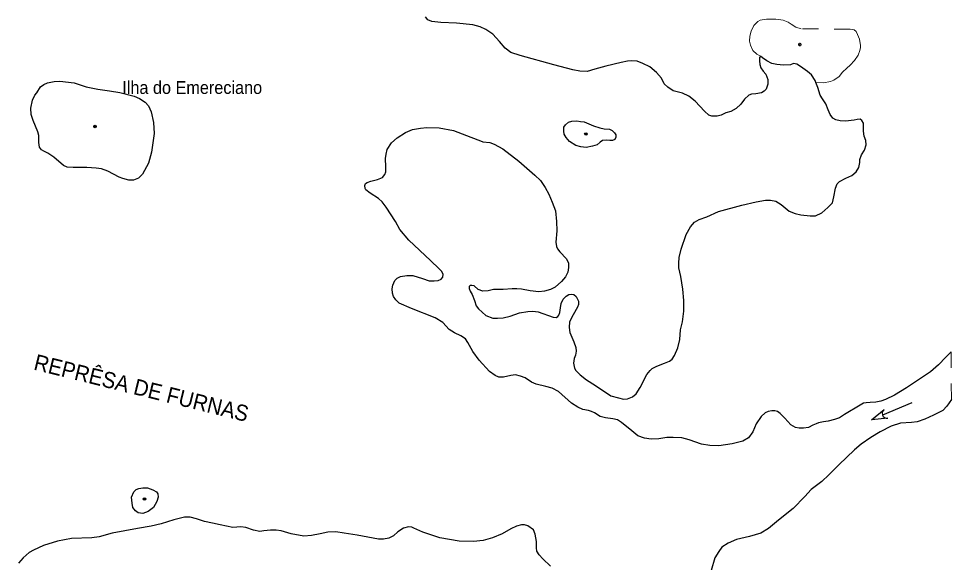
# Model space of a CAD drawing. Extents: x 396 to 422.2, y 7649.8 to 7677.6.
# Drawn here: x 416.25 to 422.09, y 7668.32 to 7671.72 of the extents above; entities that cross this region are included whole.
import ezdxf
from ezdxf.enums import TextEntityAlignment as Align

# ---------------------------------------------------------------- set-up
doc = ezdxf.new("R2010")
doc.units = 0
doc.header["$LTSCALE"] = 0.032
doc.header["$PDMODE"] = 32
doc.header["$PDSIZE"] = 0.016
doc.linetypes.add('SHORT_DASHED', pattern=[2.7, 1.5, -1.2])
for name, color, linetype, lineweight in [('10', 7, 'Continuous', 25), ('2', 7, 'Continuous', 25), ('21', 7, 'SHORT_DASHED', 13), ('62', 7, 'SHORT_DASHED', 13)]:
    doc.layers.add(name, color=color, linetype=linetype, lineweight=lineweight)
doc.layers.add('54', color=7, linetype='Continuous')
doc.layers.add('61', color=7, linetype='Continuous')

msp = doc.modelspace()

# ---------------------------------------------------------------- linework, layer by layer
at = {"layer": '10'}
msp.add_line((421.8393, 7669.321), (421.6571, 7669.2428), dxfattribs=at)
msp.add_lwpolyline([(421.6658, 7669.2782), (421.6602, 7669.2718), (421.6571, 7669.2668), (421.6548, 7669.2575), (421.6558, 7669.2462), (421.6571, 7669.2428), (421.6615, 7669.2357), (421.6669, 7669.2305), (421.6731, 7669.2264), (421.6803, 7669.2246), (421.6891, 7669.2243), (421.5883, 7669.2133)], close=True, dxfattribs=at)
at = {"layer": '2'}
msp.add_line((416.9546, 7668.7296), (416.9691, 7668.7641), dxfattribs=at)
for points in [[(420.8921, 7671.4904), (420.8871, 7671.4825), (420.8871, 7671.4609), (420.8891, 7671.4373), (420.894, 7671.4176), (420.9098, 7671.396), (420.9265, 7671.3773), (420.9392, 7671.3439), (420.9383, 7671.3144), (420.9284, 7671.2839), (420.9157, 7671.2701), (420.898, 7671.2603), (420.8635, 7671.2544), (420.836, 7671.2524), (420.8193, 7671.2456), (420.7927, 7671.222), (420.7691, 7671.1895), (420.7406, 7671.162), (420.7062, 7671.1443), (420.6747, 7671.1345), (420.6452, 7671.1217), (420.6207, 7671.1138), (420.5882, 7671.1138), (420.5685, 7671.1207), (420.541, 7671.1463), (420.484, 7671.2092), (420.4437, 7671.2397), (420.4034, 7671.2583), (420.3463, 7671.2741), (420.3129, 7671.2957), (420.2893, 7671.3173), (420.2716, 7671.3527), (420.2421, 7671.3872), (420.1988, 7671.4235), (420.1546, 7671.4452), (420.1202, 7671.458), (420.0867, 7671.4609), (420.0602, 7671.4589), (420.0199, 7671.4511), (419.9245, 7671.4285), (419.8557, 7671.4078), (419.8075, 7671.395), (419.7603, 7671.397), (419.717, 7671.4039), (419.598, 7671.4363), (419.3866, 7671.4943), (419.3296, 7671.514), (419.2932, 7671.5406), (419.2578, 7671.5828), (419.2155, 7671.6281), (419.1732, 7671.6576), (419.1369, 7671.6733), (419.0907, 7671.6861), (418.9894, 7671.6959), (418.8901, 7671.7018), (418.834, 7671.7077), (418.8094, 7671.7175), (418.7947, 7671.7362)], [(421.2398, 7671.3247), (421.2352, 7671.337), (421.2126, 7671.3724), (421.187, 7671.395), (421.1428, 7671.4245), (421.1192, 7671.4403), (421.0985, 7671.4442), (421.0808, 7671.4363), (421.0356, 7671.4344), (420.9953, 7671.4383), (420.9638, 7671.4432), (420.9324, 7671.4609), (420.9048, 7671.4796), (420.8921, 7671.4904)], [(416.3604, 7671.26), (416.3837, 7671.2973), (416.4047, 7671.3137), (416.4269, 7671.323), (416.4701, 7671.3324), (416.5051, 7671.3335), (416.5938, 7671.323), (416.6697, 7671.2973), (416.742, 7671.2845), (416.8167, 7671.2728), (416.8798, 7671.2635), (416.9708, 7671.239), (417.0035, 7671.2261), (417.0397, 7671.2028), (417.0607, 7671.1783), (417.077, 7671.1421), (417.091, 7671.0744), (417.0957, 7671.0055), (417.0782, 7670.8888), (417.0595, 7670.82), (417.0233, 7670.7523)], [(421.3286, 7671.1246), (421.3168, 7671.1541), (421.3011, 7671.1925), (421.2805, 7671.2239), (421.2667, 7671.2456), (421.251, 7671.2947), (421.2398, 7671.3247)], [(417.0233, 7670.7523), (416.9977, 7670.7266), (416.9661, 7670.7149), (416.937, 7670.7149), (416.8984, 7670.7243), (416.8763, 7670.7336), (416.8062, 7670.7709), (416.7654, 7670.7849), (416.7327, 7670.7896), (416.6743, 7670.7931), (416.5891, 7670.7931), (416.5506, 7670.7955), (416.5273, 7670.806), (416.4666, 7670.8573), (416.4292, 7670.883), (416.4047, 7670.8947), (416.3907, 7670.904), (416.3779, 7670.9203), (416.3732, 7670.9507), (416.3732, 7670.9939), (416.3674, 7671.0172), (416.337, 7671.0872), (416.3254, 7671.1258), (416.3242, 7671.1643), (416.3335, 7671.2145), (416.3487, 7671.246), (416.3604, 7671.26)], [(419.6393, 7669.9152), (419.6452, 7669.9427), (419.657, 7669.9702), (419.6757, 7669.9879), (419.6914, 7669.9978), (419.7082, 7669.9997), (419.7239, 7669.9978), (419.7377, 7669.986), (419.7534, 7669.9574), (419.7524, 7669.9368), (419.7475, 7669.9201), (419.72, 7669.8709), (419.6954, 7669.8267), (419.6934, 7669.7913), (419.6983, 7669.7598), (419.7229, 7669.7028), (419.7367, 7669.6664), (419.7386, 7669.6428), (419.7337, 7669.6192), (419.7249, 7669.5976), (419.7219, 7669.5681), (419.7278, 7669.5376), (419.7357, 7669.5218), (419.7622, 7669.4953), (419.8026, 7669.4638), (419.8586, 7669.4294), (419.956, 7669.3645), (420.0032, 7669.3508), (420.0346, 7669.3429), (420.0602, 7669.3458), (420.0907, 7669.3576), (420.1133, 7669.3773), (420.1388, 7669.4166), (420.1811, 7669.4982), (420.2008, 7669.5238), (420.2146, 7669.5356), (420.2441, 7669.5494), (420.2903, 7669.5681), (420.3227, 7669.5808), (420.3394, 7669.5946), (420.3542, 7669.6162), (420.3739, 7669.6644), (420.3876, 7669.7165), (420.3916, 7669.7765), (420.4034, 7669.8267), (420.4122, 7669.8935), (420.4122, 7669.9604), (420.4063, 7670.0312), (420.3935, 7670.1108), (420.3817, 7670.1659), (420.3817, 7670.1954), (420.3837, 7670.2298), (420.3965, 7670.2819), (420.427, 7670.3734), (420.4545, 7670.4216), (420.48, 7670.4511), (420.5086, 7670.4678), (420.5558, 7670.4855), (420.6295, 7670.5169), (420.776, 7670.5582), (420.8645, 7670.5789), (420.9245, 7670.5887), (420.956, 7670.5887), (420.9874, 7670.5818), (421.0228, 7670.5622), (421.072, 7670.5199), (421.1094, 7670.5051), (421.1457, 7670.4963), (421.2038, 7670.4914), (421.2372, 7670.4914), (421.2775, 7670.5101), (421.3149, 7670.5425), (421.3434, 7670.573), (421.3513, 7670.6094), (421.3621, 7670.6635), (421.3729, 7670.691), (421.3876, 7670.7048), (421.426, 7670.7274), (421.4653, 7670.7431), (421.4919, 7670.7667), (421.5076, 7670.7932), (421.5135, 7670.8247), (421.5135, 7670.8444), (421.5243, 7670.8729), (421.544, 7670.9024), (421.5548, 7670.9358), (421.5518, 7670.9614), (421.542, 7670.9889), (421.5371, 7671.0214), (421.5381, 7671.044), (421.5371, 7671.0705), (421.5273, 7671.0873), (421.5155, 7671.0961), (421.4987, 7671.0941), (421.4781, 7671.0892)], [(421.4781, 7671.0892), (421.424, 7671.0823), (421.3916, 7671.0853), (421.364, 7671.0912), (421.3454, 7671.103), (421.3286, 7671.1246)], [(418.8488, 7670.0843), (418.8743, 7670.0853), (418.892, 7670.0951), (418.9038, 7670.1069), (418.9048, 7670.1266), (418.895, 7670.1443), (418.8802, 7670.16), (418.8252, 7670.2121), (418.6904, 7670.338), (418.6344, 7670.4058), (418.6059, 7670.455), (418.5479, 7670.5455), (418.5243, 7670.5779), (418.4997, 7670.5995), (418.4486, 7670.633), (418.422, 7670.6526), (418.4161, 7670.6625), (418.4141, 7670.6802), (418.4191, 7670.693), (418.4289, 7670.6998), (418.4525, 7670.7087), (418.4948, 7670.7175), (418.5253, 7670.7313), (418.54, 7670.749), (418.5459, 7670.7657), (418.5459, 7670.7972), (418.5449, 7670.8493), (418.5479, 7670.8778), (418.5548, 7670.9053), (418.5813, 7670.9476), (418.6167, 7670.9791), (418.6688, 7671.0125), (418.714, 7671.0302), (418.7632, 7671.0401), (418.8035, 7671.044), (418.8802, 7671.041), (418.9707, 7671.0243), (419.0779, 7670.983), (419.1388, 7670.9594), (419.1546, 7670.9545), (419.1968, 7670.9496), (419.2254, 7670.9388), (419.2785, 7670.9093), (419.3788, 7670.8336), (419.4791, 7670.7451), (419.5154, 7670.7126), (419.5449, 7670.6674), (419.5666, 7670.6261), (419.5872, 7670.5769), (419.6088, 7670.5228), (419.6157, 7670.455), (419.6177, 7670.397), (419.6108, 7670.3262), (419.6147, 7670.2996), (419.6216, 7670.2839), (419.6364, 7670.2652), (419.6767, 7670.221), (419.6905, 7670.1944), (419.6905, 7670.1679), (419.6865, 7670.1374), (419.6718, 7670.1089), (419.6462, 7670.0794), (419.6069, 7670.045), (419.5774, 7670.0302), (419.54, 7670.0194), (419.5036, 7670.0155), (419.4496, 7670.0204), (419.3955, 7670.0312), (419.366, 7670.0341), (419.3365, 7670.0332), (419.2814, 7670.0292), (419.2214, 7670.0292), (419.187, 7670.0214), (419.1546, 7670.0184), (419.1251, 7670.0302), (419.0985, 7670.0518), (419.0857, 7670.0548), (419.0739, 7670.0548), (419.0671, 7670.0489), (419.0671, 7670.0351), (419.0749, 7670.0194), (419.0877, 7669.9978), (419.1005, 7669.9604), (419.1123, 7669.9279), (419.127, 7669.9093), (419.1732, 7669.868), (419.2165, 7669.8503), (419.246, 7669.8503), (419.2814, 7669.8522), (419.3247, 7669.863), (419.3837, 7669.8827), (419.4348, 7669.8925), (419.4663, 7669.8945), (419.4997, 7669.8906), (419.5941, 7669.8562)], [(419.6971, 7670.9554), (419.6751, 7670.981), (419.6637, 7671.0012), (419.6602, 7671.0214), (419.6602, 7671.0452), (419.6707, 7671.061), (419.691, 7671.0769), (419.7112, 7671.0839), (419.7429, 7671.0848), (419.7658, 7671.0821), (419.7886, 7671.0795)], [(419.7886, 7671.0795), (419.8476, 7671.0531), (419.8854, 7671.0417), (419.9136, 7671.0355), (419.9479, 7671.0329), (419.9646, 7671.0258), (419.9787, 7671.0109), (419.9857, 7670.9986), (419.9857, 7670.9827), (419.9796, 7670.9686), (419.9655, 7670.9616), (419.9488, 7670.9616), (419.925, 7670.9642), (419.9039, 7670.9625), (419.889, 7670.951), (419.8687, 7670.9352), (419.8414, 7670.9264), (419.8001, 7670.9194), (419.7666, 7670.922), (419.7367, 7670.9308), (419.6971, 7670.9554)], [(422.086, 7669.6405), (422.0533, 7669.6054), (422.0071, 7669.5582), (421.956, 7669.515), (421.8999, 7669.4776), (421.8075, 7669.4137), (421.7318, 7669.3694), (421.6757, 7669.3419), (421.6453, 7669.3311), (421.6148, 7669.3252), (421.5784, 7669.3222), (421.5538, 7669.3213), (421.5371, 7669.3173), (421.5155, 7669.3065), (421.4191, 7669.2475), (421.3866, 7669.2269), (421.3552, 7669.2151), (421.3168, 7669.2052), (421.2864, 7669.2023), (421.2549, 7669.1954), (421.2411, 7669.1895), (421.2195, 7669.1797), (421.192, 7669.1669), (421.1615, 7669.161), (421.1349, 7669.162), (421.1113, 7669.1659), (421.0818, 7669.1836), (421.0445, 7669.2239), (421.015, 7669.2534), (420.9982, 7669.2652), (420.9815, 7669.2701), (420.9638, 7669.2711), (420.9402, 7669.2652), (420.9215, 7669.2573), (420.897, 7669.2347), (420.8645, 7669.1895), (420.8449, 7669.1393), (420.8163, 7669.101), (420.7809, 7669.0813), (420.716, 7669.0636), (420.6315, 7669.0518), (420.5744, 7669.0538), (420.5223, 7669.0626), (420.4456, 7669.0892), (420.3994, 7669.101), (420.3453, 7669.103), (420.306, 7669.103), (420.2568, 7669.0941), (420.2087, 7669.0921), (420.1664, 7669.099), (420.1251, 7669.1148), (420.0857, 7669.1462), (420.0218, 7669.1983), (419.9963, 7669.2131), (419.9668, 7669.22), (419.9215, 7669.2269), (419.8891, 7669.2357), (419.8537, 7669.2573), (419.834, 7669.2672), (419.8144, 7669.2721), (419.779, 7669.279), (419.7495, 7669.2937), (419.7082, 7669.3193), (419.6275, 7669.3911), (419.5882, 7669.4117), (419.5479, 7669.4225), (419.4869, 7669.4363), (419.4574, 7669.4501), (419.4181, 7669.4766), (419.3896, 7669.4874), (419.3591, 7669.4953), (419.3286, 7669.4923), (419.2824, 7669.4815), (419.2549, 7669.4815), (419.2303, 7669.4914), (419.1959, 7669.5169), (419.131, 7669.5877), (419.0907, 7669.6408), (419.0592, 7669.6988), (419.0444, 7669.7205), (419.0169, 7669.7401), (418.9756, 7669.7578), (418.9432, 7669.7795), (418.9028, 7669.8227), (418.8547, 7669.8522), (418.7072, 7669.9102), (418.6295, 7669.9447), (418.6088, 7669.9643), (418.5941, 7669.986), (418.5882, 7670.0076), (418.5862, 7670.0332), (418.5911, 7670.0568), (418.6029, 7670.0863), (418.6167, 7670.101), (418.6374, 7670.1118)], [(418.6374, 7670.1118), (418.6777, 7670.1177), (418.715, 7670.1167), (418.775, 7670.099), (418.8173, 7670.0843), (418.8488, 7670.0843)], [(419.5941, 7669.8562), (419.6128, 7669.8552), (419.6226, 7669.8601), (419.6295, 7669.8689), (419.6354, 7669.8857), (419.6393, 7669.9152)], [(422.0875, 7669.3403), (422.0582, 7669.3006), (422.0346, 7669.2731), (421.9766, 7669.2426), (421.9216, 7669.218), (421.8744, 7669.2013), (421.837, 7669.1964), (421.7682, 7669.1934), (421.7111, 7669.1747), (421.6413, 7669.1393), (421.5823, 7669.1039), (421.5223, 7669.0607), (421.481, 7669.0263), (421.3837, 7668.9319), (421.3208, 7668.8699), (421.2765, 7668.8276), (421.2106, 7668.7775), (421.1703, 7668.7342), (421.0966, 7668.6595), (421.0061, 7668.5857), (420.9422, 7668.5336), (420.894, 7668.5041), (420.8232, 7668.4845), (420.7426, 7668.4648), (420.6905, 7668.4422), (420.6502, 7668.4166), (420.6305, 7668.3901), (420.6069, 7668.3498), (420.5833, 7668.2711)], [(416.9691, 7668.7641), (416.9835, 7668.7775), (416.9991, 7668.7842), (417.0236, 7668.7875), (417.0537, 7668.7875), (417.0871, 7668.7764), (417.1093, 7668.7641), (417.1194, 7668.7508), (417.1205, 7668.7307), (417.1127, 7668.7029), (417.0904, 7668.665), (417.057, 7668.6394), (417.0247, 7668.6283), (416.9947, 7668.6327), (416.978, 7668.6439), (416.9624, 7668.665), (416.9568, 7668.6929), (416.9546, 7668.7296)], [(419.5764, 7668.2986), (419.5292, 7668.3439), (419.5056, 7668.3694), (419.4928, 7668.392), (419.4889, 7668.4127), (419.4889, 7668.452), (419.482, 7668.4992), (419.4702, 7668.5248), (419.4358, 7668.5503), (419.4142, 7668.5562), (419.3965, 7668.5562), (419.364, 7668.5494), (419.3296, 7668.5326), (419.2755, 7668.5012), (419.2136, 7668.4756), (419.1565, 7668.4589), (419.0956, 7668.453), (419.0051, 7668.454), (418.8851, 7668.4756), (418.778, 7668.511), (418.7219, 7668.5366), (418.7101, 7668.5425), (418.6885, 7668.5435), (418.656, 7668.5356), (418.6216, 7668.514), (418.5951, 7668.4874), (418.5656, 7668.4737), (418.5321, 7668.4668), (418.4997, 7668.4678), (418.3669, 7668.4913), (418.2863, 7668.5051), (418.2332, 7668.514), (418.1841, 7668.512), (418.1349, 7668.5002), (418.0808, 7668.4904), (418.0326, 7668.4864), (417.954, 7668.5012), (417.891, 7668.5189), (417.8605, 7668.5228), (417.8242, 7668.5238), (417.7829, 7668.5189), (417.7563, 7668.5159), (417.717, 7668.5238), (417.6698, 7668.5405), (417.6393, 7668.5435), (417.5892, 7668.5405), (417.5095, 7668.5562), (417.4613, 7668.568), (417.4112, 7668.5769), (417.361, 7668.5936), (417.3207, 7668.6054), (417.2853, 7668.6044), (417.2185, 7668.5887), (417.1388, 7668.5621), (417.0759, 7668.5484), (416.9913, 7668.5346), (416.833, 7668.5041), (416.7514, 7668.4815), (416.7052, 7668.4746), (416.5773, 7668.4717), (416.4898, 7668.454), (416.4023, 7668.4265), (416.3404, 7668.3989), (416.3119, 7668.3842), (416.2745, 7668.3507), (416.247, 7668.3163)]]:
    msp.add_lwpolyline(points, dxfattribs=at)
at = {"layer": '21'}
msp.add_lwpolyline([(421.2398, 7671.3247), (421.2879, 7671.3228), (421.3299, 7671.3314), (421.3514, 7671.34), (421.3847, 7671.3637), (421.4052, 7671.3906), (421.4321, 7671.4153), (421.4536, 7671.4347), (421.4816, 7671.4638), (421.5042, 7671.496), (421.5139, 7671.5262), (421.5182, 7671.5434), (421.5182, 7671.5574), (421.5117, 7671.5972), (421.4988, 7671.6262), (421.4913, 7671.6445), (421.4794, 7671.6553), (421.4547, 7671.6585), (421.147, 7671.6617), (421.1136, 7671.6714), (421.0835, 7671.6908), (421.0652, 7671.7026), (421.0351, 7671.7144), (420.9877, 7671.7209), (420.9296, 7671.722), (420.8909, 7671.7144), (420.8759, 7671.7069), (420.8511, 7671.6811), (420.8339, 7671.6467), (420.8264, 7671.6155), (420.8242, 7671.5843), (420.8296, 7671.5584), (420.8447, 7671.5262), (420.8694, 7671.5036), (420.8921, 7671.4904)], dxfattribs=at)
msp.add_point((421.1384, 7671.5627), dxfattribs=at)
at = {"layer": '54'}
for p in [(416.7252, 7671.0501), (419.7992, 7671.0029), (417.0352, 7668.7182)]:
    msp.add_point(p, dxfattribs=at)
at = {"layer": '62'}
msp.add_line((422.086, 7669.6405), (422.0875, 7669.3403), dxfattribs=at)

# ---------------------------------------------------------------- texts
at = {"layer": '54', "width": 0.95}
msp.add_text('Ilha do Emereciano', height=0.08, dxfattribs=at).set_placement((416.896, 7671.2538))
at = {"layer": '61', "width": 0.95}
msp.add_text('REPRÊSA DE FURNAS', height=0.1, rotation=346.18, dxfattribs=at).set_placement((417.004, 7669.365), align=Align.CENTER)

doc.saveas('drawing.dxf')
